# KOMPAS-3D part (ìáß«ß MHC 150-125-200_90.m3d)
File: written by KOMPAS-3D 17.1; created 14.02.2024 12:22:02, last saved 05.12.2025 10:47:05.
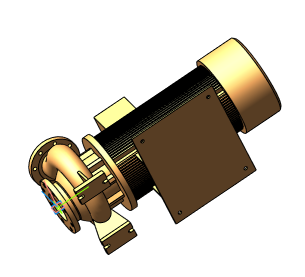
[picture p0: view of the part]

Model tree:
1. Операция без истории:3

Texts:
  ООО АДЛ Групп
